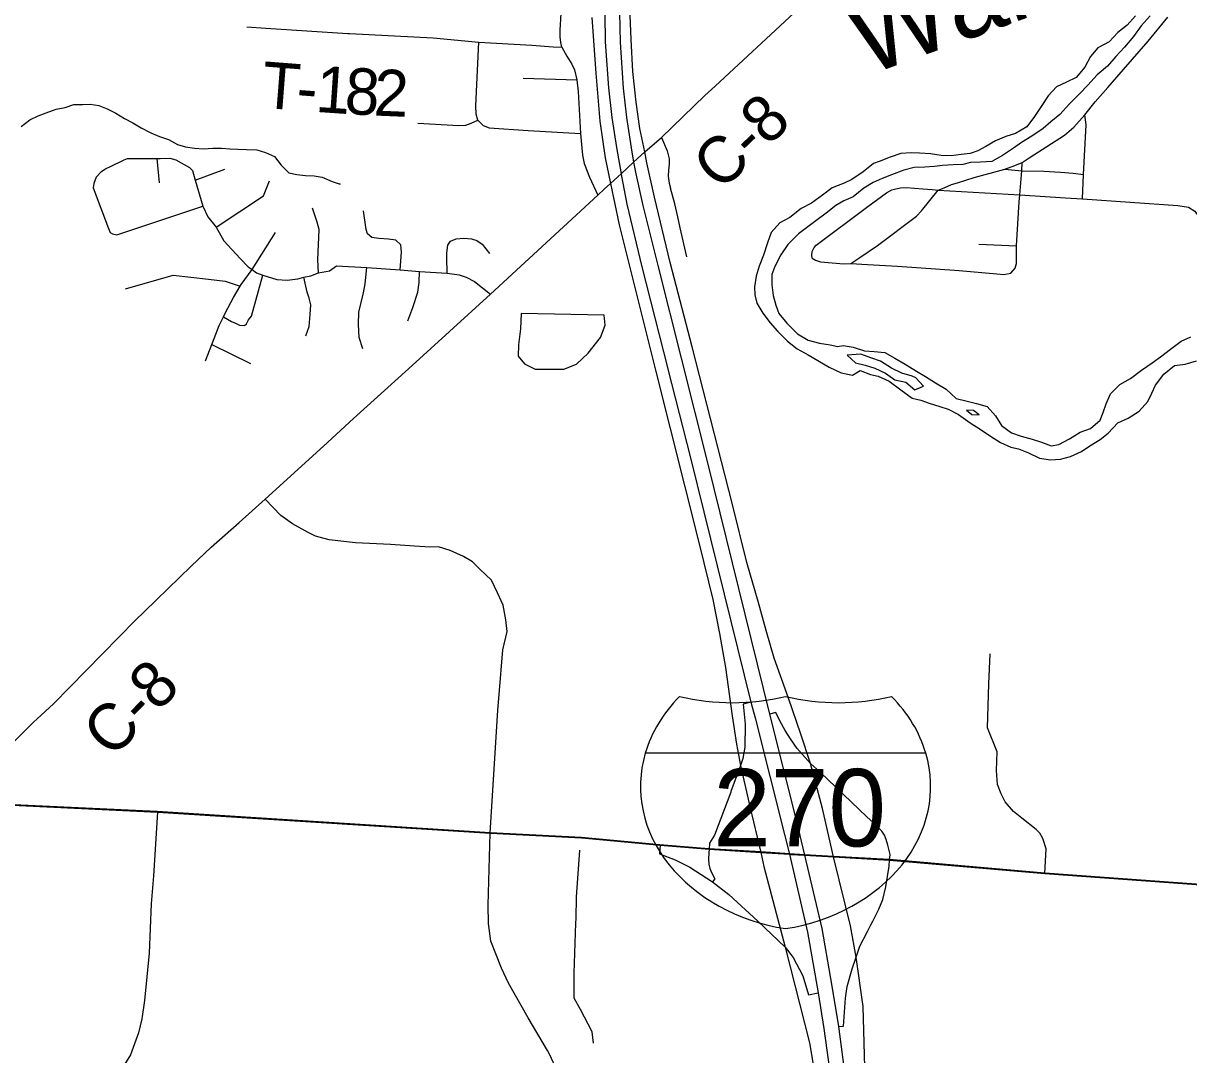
# Model space of a CAD drawing. Extents: x 0 to 34, y 0 to 22.
# Drawn here: x 5.335 to 6.761, y 16 to 17.262 of the extents above; entities that cross this region are included whole.
import ezdxf

# ---------------------------------------------------------------- set-up
doc = ezdxf.new("R2010")
doc.units = 0
for name, color, linetype in [('GM_X_City_Street', 7, 'Continuous'), ('GM_X_County_Road', 7, 'Continuous'), ('GM_X_County_Road_Text', 7, 'Continuous'), ('GM_X_Interchange_Ramps', 7, 'Continuous'), ('GM_X_Interstate_Location', 7, 'Continuous'), ('GM_X_Interstate_Route', 7, 'Continuous'), ('GM_X_Interstate_Shield', 7, 'Continuous'), ('GM_X_Major_River', 7, 'Continuous'), ('GM_X_Major_River_Text', 7, 'Continuous'), ('GM_X_Minor_Lake', 7, 'Continuous'), ('GM_X_Minor_River', 7, 'Continuous'), ('GM_X_Township_Road', 7, 'Continuous'), ('GM_X_Township_Road_Text', 7, 'Continuous')]:
    doc.layers.add(name, color=color, linetype=linetype)

msp = doc.modelspace()

# ---------------------------------------------------------------- linework, layer by layer
at = {"layer": 'GM_X_City_Street'}
for p, q in [((5.6084, 17.2578), (5.6319, 17.2559)), ((5.9467, 17.1948), (6.0123, 17.1929)), ((5.5015, 17.067), (5.4987, 17.0966)), ((5.5454, 17.07), (5.5815, 17.0837)), ((5.6149, 16.9609), (5.6436, 17.006)), ((6.5039, 16.9917), (6.5499, 16.9899)), ((5.5657, 16.869), (5.6129, 16.8458))]:
    msp.add_line(p, q, dxfattribs=at)
for points in [[(5.9939, 17.2327), (5.9927, 17.2383), (5.9918, 17.2453), (5.9918, 17.2535), (5.993, 17.2739)], [(6.2999, 16.9746), (6.2995, 16.9783), (6.3002, 16.983), (6.3026, 16.9877), (6.3051, 16.9905), (6.3682, 17.038), (6.3912, 17.0545), (6.3974, 17.0581), (6.4025, 17.0595), (6.408, 17.0608), (6.4149, 17.0612), (6.4354, 17.0594), (6.447, 17.0588), (6.4542, 17.0579), (6.4617, 17.0607), (6.4707, 17.0646), (6.4779, 17.0668), (6.4981, 17.0734), (6.5356, 17.0837), (6.5482, 17.0881), (6.5569, 17.0916), (6.5656, 17.0976), (6.6087, 17.1251), (6.6201, 17.1351), (6.6338, 17.1499), (6.6464, 17.1658), (6.6619, 17.1835), (6.7111, 17.2403), (6.7352, 17.2694)], [(5.8911, 17.1436), (5.8889, 17.1509), (5.8885, 17.1612), (5.8921, 17.2387)], [(5.8175, 17.14), (5.868, 17.1371), (5.8765, 17.1375), (5.883, 17.1399), (5.8911, 17.1436)], [(5.8911, 17.1436), (5.8976, 17.1369), (5.9051, 17.1339), (5.9526, 17.131), (6.0165, 17.1271)], [(6.6309, 17.0471), (6.632, 17.077), (6.6353, 17.1377), (6.6338, 17.1499)], [(5.4243, 17.0738), (5.4305, 17.0805), (5.4348, 17.0834), (5.4544, 17.0929), (5.4586, 17.0951), (5.4626, 17.0965), (5.4961, 17.0967), (5.4987, 17.0966), (5.5025, 17.0966), (5.5143, 17.0969), (5.5218, 17.0949), (5.5384, 17.0856), (5.5418, 17.0818), (5.5454, 17.07)], [(6.5356, 17.0837), (6.5567, 17.0815), (6.5833, 17.0809), (6.6039, 17.08), (6.6192, 17.0785), (6.632, 17.077)], [(6.543, 16.9562), (6.5486, 16.9623), (6.5499, 16.9682), (6.5499, 16.9899), (6.5532, 17.0435), (6.5541, 17.0522), (6.5567, 17.0815), (6.5569, 17.0916)], [(5.4243, 17.0738), (5.4212, 17.0659), (5.4204, 17.0606), (5.4392, 17.0111), (5.4414, 17.0061), (5.4441, 17.0046), (5.4494, 17.0034), (5.5547, 17.0381)], [(5.5454, 17.07), (5.5547, 17.0381), (5.5609, 17.0254), (5.5708, 17.0126), (5.5803, 16.996), (5.6002, 16.9742), (5.6103, 16.9642), (5.6149, 16.9609), (5.6204, 16.9569), (5.6279, 16.9538), (5.6453, 16.9487), (5.6578, 16.9478), (5.6707, 16.9496), (5.6781, 16.9513), (5.6867, 16.9532), (5.6962, 16.9567), (5.7094, 16.9591), (5.7182, 16.9652), (5.7551, 16.9631), (5.7962, 16.9605), (5.8198, 16.9582), (5.8534, 16.9565), (5.8682, 16.9543), (5.8766, 16.9514), (5.8868, 16.9463), (5.9065, 16.9306)], [(5.5708, 17.0126), (5.6289, 17.051), (5.6363, 17.0691)], [(6.1469, 16.9765), (6.1386, 17.0119), (6.1358, 17.0251), (6.132, 17.0412), (6.1267, 17.0604)], [(6.3473, 16.9683), (6.3583, 16.9755), (6.3798, 16.9902), (6.4278, 17.0261), (6.4339, 17.0326), (6.4542, 17.0579)], [(6.4542, 17.0579), (6.5541, 17.0522), (6.61, 17.0483), (6.6309, 17.0471), (6.7473, 17.0393), (6.7603, 17.0371), (6.7684, 17.0323), (6.7728, 17.0256), (6.7751, 17.0168), (6.7743, 17.0001), (6.7758, 16.9901), (6.778, 16.9853), (6.7861, 16.9783), (6.7969, 16.975), (6.8405, 16.9724), (6.8756, 16.9717), (6.9809, 16.9547)], [(5.6962, 16.9567), (5.6952, 16.9725), (5.6971, 17.0097), (5.6945, 17.0188), (5.689, 17.036)], [(5.7962, 16.9605), (5.7976, 16.982), (5.7967, 16.9911), (5.7908, 16.9965), (5.7817, 16.9981), (5.7698, 16.9986), (5.7612, 17), (5.7562, 17.0044), (5.7546, 17.0099), (5.7511, 17.0327)], [(5.8534, 16.9565), (5.853, 16.9754), (5.8532, 16.9813), (5.8543, 16.9904), (5.8578, 16.9954), (5.8644, 16.9982), (5.8739, 16.999), (5.8832, 16.9982), (5.8897, 16.9961), (5.8963, 16.9919), (5.9054, 16.9802)], [(6.2999, 16.9746), (6.304, 16.9722), (6.3103, 16.9702), (6.339, 16.9677), (6.3473, 16.9683), (6.3676, 16.967), (6.4043, 16.9649), (6.4799, 16.9596), (6.5258, 16.9557), (6.5345, 16.9549), (6.543, 16.9562)], [(5.4601, 16.9372), (5.5182, 16.9538), (5.5617, 16.9488), (5.5821, 16.9467), (5.6003, 16.9406)], [(5.558, 16.849), (5.5657, 16.869), (5.5666, 16.8713), (5.5747, 16.8925), (5.5798, 16.9029), (5.5821, 16.9076), (5.5921, 16.9265), (5.6003, 16.9406), (5.6014, 16.9423), (5.6149, 16.9609)], [(5.5798, 16.9029), (5.5899, 16.8973), (5.5956, 16.8949), (5.5997, 16.8926), (5.6058, 16.8922), (5.6081, 16.8944), (5.6104, 16.8993), (5.6142, 16.9038), (5.6279, 16.9538)], [(5.6806, 16.8797), (5.6849, 16.891), (5.6858, 16.9058), (5.6867, 16.9176), (5.6849, 16.9259), (5.6823, 16.9332), (5.6781, 16.9513)], [(5.7504, 16.8638), (5.7457, 16.8778), (5.745, 16.8937), (5.7453, 16.9086), (5.7511, 16.9322), (5.7534, 16.9432), (5.7551, 16.9631)], [(5.8055, 16.8981), (5.8116, 16.9142), (5.8175, 16.9329), (5.8191, 16.9451), (5.8198, 16.9582)], [(6.5847, 16.222), (6.5864, 16.2522), (6.5821, 16.2649), (6.5784, 16.2713), (6.574, 16.2759), (6.5566, 16.2897), (6.5462, 16.2977), (6.5362, 16.3097), (6.5312, 16.3195), (6.5268, 16.3308), (6.5255, 16.3479), (6.5262, 16.3707), (6.5145, 16.4004), (6.5162, 16.4539), (6.5179, 16.4906)], [(5.4991, 16.2971), (5.4941, 16.2193), (5.4913, 16.1851), (5.4888, 16.1248), (5.4834, 16.0669), (5.4802, 16.0443), (5.4758, 16.027), (5.4661, 16.0004), (5.4486, 15.9722), (5.4357, 15.9514), (5.4266, 15.9386), (5.4187, 15.9225), (5.4119, 15.9062), (5.4097, 15.8987), (5.4079, 15.8916), (5.4039, 15.8634), (5.4034, 15.8376), (5.403, 15.8068), (5.397, 15.7237), (5.3963, 15.6548), (5.395, 15.6065), (5.3941, 15.5706), (5.3958, 15.5456), (5.3958, 15.4747)], [(6.0325, 16.0147), (6.0311, 16.0282), (6.0168, 16.0557), (6.0088, 16.0696), (6.0091, 16.1003), (6.0111, 16.1613), (6.0113, 16.1672), (6.0117, 16.1932), (6.0158, 16.2504)]]:
    msp.add_lwpolyline(points, dxfattribs=at)
at = {"layer": 'GM_X_County_Road'}
msp.add_line((5.3406, 16.4002), (5.3476, 16.4072), dxfattribs=at)
for points in [[(6.1813, 17.1852), (6.3745, 17.3648), (6.5248, 17.5102), (6.5981, 17.5821), (6.6226, 17.6074), (6.632, 17.6186), (6.6405, 17.6299), (6.6463, 17.639), (6.6511, 17.6472), (6.6555, 17.6548), (6.6616, 17.6661), (6.6675, 17.6806), (6.6714, 17.6936), (6.6742, 17.7018), (6.6745, 17.7027)], [(6.0456, 17.059), (6.0535, 17.0662), (6.0664, 17.078), (6.0814, 17.092), (6.0952, 17.1048), (6.1156, 17.1224), (6.1688, 17.1735), (6.1813, 17.1852)], [(5.5487, 16.6058), (5.565, 16.621), (5.5989, 16.6512), (5.6311, 16.6797), (5.7021, 16.7449), (5.7389, 16.7787), (5.8062, 16.8393), (5.9065, 16.9306), (6.0378, 17.0517), (6.0456, 17.059)], [(5.9172, 16.4408), (5.9218, 16.4955), (5.9268, 16.5182), (5.9255, 16.5323), (5.922, 16.5502), (5.9152, 16.5655), (5.9077, 16.5809), (5.8941, 16.5937), (5.8845, 16.6033), (5.8736, 16.6097), (5.8572, 16.6173), (5.8429, 16.6218), (5.8322, 16.6212), (5.8137, 16.6226), (5.7841, 16.6245), (5.7415, 16.6266), (5.7092, 16.6301), (5.6926, 16.6348), (5.6834, 16.6391), (5.6643, 16.6498), (5.6502, 16.6598), (5.6311, 16.6797)], [(5.4834, 16.5425), (5.5405, 16.5981), (5.5487, 16.6058)], [(5.3476, 16.4072), (5.3518, 16.4114), (5.3721, 16.4296), (5.4718, 16.5313), (5.4834, 16.5425)], [(5.9063, 16.2713), (5.9156, 16.4219), (5.9172, 16.4408)], [(5.2617, 16.3084), (5.2893, 16.3473), (5.3052, 16.3647), (5.3204, 16.3801), (5.3399, 16.3995), (5.3406, 16.4002)], [(5.2615, 16.3089), (5.4989, 16.2977), (5.9061, 16.2718), (6.0177, 16.2662), (6.1138, 16.2573), (6.1738, 16.2523), (6.2371, 16.2484), (6.2723, 16.246), (6.2905, 16.245), (6.3259, 16.243), (6.3946, 16.239), (6.5845, 16.2226), (6.9775, 16.1941), (7.1913, 16.1774), (7.4185, 16.1629), (7.5307, 16.155), (7.5899, 16.1511), (7.7224, 16.142), (8.0841, 16.1202)], [(8.0841, 16.1202), (7.7224, 16.142), (7.5899, 16.1511), (7.5307, 16.155), (7.4185, 16.1629), (7.1913, 16.1774), (6.9775, 16.1941), (6.5845, 16.2226), (6.3946, 16.239), (6.3259, 16.243), (6.2905, 16.245), (6.2723, 16.246), (6.2371, 16.2484), (6.1738, 16.2523), (6.1138, 16.2573), (6.0177, 16.2662), (5.9061, 16.2718), (5.4989, 16.2977), (5.2615, 16.3089)], [(5.2617, 16.3084), (5.4991, 16.2971), (5.9063, 16.2713), (6.018, 16.2657), (6.0267, 16.2649)], [(5.9761, 16.0057), (5.9528, 16.0456), (5.9287, 16.0877), (5.9201, 16.1062), (5.907, 16.1391), (5.9043, 16.1607), (5.9037, 16.1834), (5.9063, 16.2713)], [(6.0267, 16.2649), (6.114, 16.2567), (6.174, 16.2518)], [(6.174, 16.2518), (6.2374, 16.2478), (6.2725, 16.2455), (6.2745, 16.2454)], [(6.2745, 16.2454), (6.2907, 16.2444), (6.3262, 16.2424), (6.3948, 16.2385)], [(6.3948, 16.2385), (6.5847, 16.222), (6.9777, 16.1936), (7.1915, 16.1769), (7.4187, 16.1623), (7.531, 16.1545), (7.5902, 16.1505), (7.7226, 16.1415), (8.0843, 16.1197), (8.277, 16.1089)], [(5.9763, 15.5648), (5.9785, 15.6152), (5.9878, 15.7911), (5.9894, 15.8846), (5.9918, 15.9482), (5.9908, 15.9667), (5.9879, 15.9813), (5.9793, 16.0003), (5.9761, 16.0057)]]:
    msp.add_lwpolyline(points, dxfattribs=at)
at = {"layer": 'GM_X_Interchange_Ramps'}
for points in [[(6.0306, 17.269), (6.0353, 17.201), (6.0402, 17.1424), (6.0469, 17.0976), (6.0535, 17.0662), (6.064, 17.0153), (6.1084, 16.8377), (6.1623, 16.6238), (6.1787, 16.5571), (6.1869, 16.5155), (6.1939, 16.4742), (6.2022, 16.415), (6.2074, 16.3803), (6.2123, 16.3543), (6.2237, 16.304), (6.2374, 16.2478), (6.2408, 16.2307), (6.2671, 16.1321), (6.2967, 16.015), (6.3167, 15.8958)], [(6.3648, 15.9703), (6.3623, 16.0595), (6.3537, 16.1197), (6.347, 16.1582), (6.3262, 16.2424), (6.3127, 16.3016), (6.2982, 16.3565), (6.2862, 16.3926), (6.2713, 16.4363), (6.2536, 16.4856), (6.2438, 16.5192), (6.2341, 16.5546), (6.2201, 16.6025), (6.2028, 16.6735), (6.1533, 16.8663), (6.1265, 16.9695), (6.1073, 17.0491), (6.0979, 17.0914), (6.0952, 17.1048), (6.0893, 17.1331), (6.0848, 17.1655), (6.0808, 17.2031), (6.0788, 17.2421), (6.0774, 17.2718)], [(6.2252, 16.4318), (6.2155, 16.429), (6.2182, 16.4045), (6.2177, 16.3764), (6.2154, 16.3628), (6.2123, 16.3543), (6.2007, 16.3225)], [(6.3948, 16.2385), (6.3956, 16.2454), (6.3926, 16.2569), (6.3906, 16.2637), (6.3885, 16.269), (6.3852, 16.2738), (6.3796, 16.2798), (6.367, 16.2913), (6.3099, 16.3459), (6.2982, 16.3565), (6.2817, 16.3751), (6.2736, 16.3866), (6.267, 16.3971), (6.2606, 16.4087), (6.2558, 16.419), (6.2478, 16.4169)], [(6.2007, 16.3225), (6.2004, 16.3215), (6.1806, 16.269), (6.1745, 16.259), (6.174, 16.2518)], [(6.114, 16.2567), (6.1133, 16.2459), (6.1324, 16.2389), (6.1504, 16.2298), (6.178, 16.2117)], [(6.174, 16.2518), (6.1737, 16.2474), (6.1731, 16.2395), (6.1735, 16.2334), (6.1748, 16.2283), (6.1775, 16.2226), (6.1811, 16.2156), (6.178, 16.2117)], [(6.3717, 16.1591), (6.3743, 16.1639), (6.3818, 16.1785), (6.3865, 16.1902), (6.3902, 16.2057), (6.3941, 16.2309), (6.3948, 16.2385)], [(6.178, 16.2117), (6.1983, 16.1962), (6.2334, 16.1637), (6.2671, 16.1321), (6.2768, 16.1194), (6.2885, 16.0969), (6.2956, 16.0735), (6.3073, 16.076)], [(6.3321, 16.0348), (6.3382, 16.0355), (6.3408, 16.0696), (6.343, 16.0838), (6.3488, 16.1055), (6.3537, 16.1197), (6.3583, 16.133), (6.3677, 16.1513), (6.3717, 16.1591)]]:
    msp.add_lwpolyline(points, dxfattribs=at)
at = {"layer": 'GM_X_Interstate_Route'}
for points in [[(6.0806, 17.8866), (6.0801, 17.8781), (6.0749, 17.7945), (6.0705, 17.7209), (6.0641, 17.6239), (6.0455, 17.3114), (6.0469, 17.2452)], [(6.0635, 17.3111), (6.065, 17.2389), (6.069, 17.1828), (6.0729, 17.1466), (6.0786, 17.1097), (6.0814, 17.092), (6.0844, 17.0777), (6.0931, 17.0391), (6.1115, 16.9641), (6.14, 16.8524), (6.172, 16.7243), (6.2478, 16.4169), (6.2811, 16.2857), (6.2907, 16.2444), (6.3118, 16.1548), (6.3243, 16.0844), (6.3321, 16.0348), (6.3409, 15.9698), (6.3497, 15.8891), (6.3545, 15.8244), (6.3582, 15.7404), (6.3582, 15.7334)], [(6.0469, 17.2452), (6.047, 17.2392), (6.051, 17.1831), (6.0549, 17.1469), (6.0606, 17.11), (6.0664, 17.078), (6.0669, 17.075)], [(6.0669, 17.075), (6.0733, 17.0409), (6.0918, 16.9642), (6.1183, 16.8602), (6.1281, 16.8215)], [(6.1281, 16.8215), (6.1512, 16.7304), (6.2252, 16.4318)], [(6.2252, 16.4318), (6.2302, 16.4124), (6.2663, 16.2697)], [(6.2663, 16.2697), (6.2725, 16.2455), (6.2942, 16.1503), (6.3073, 16.076), (6.3144, 16.0325), (6.3232, 15.9676), (6.3319, 15.8868), (6.335, 15.8335), (6.3387, 15.7419), (6.3382, 15.6997)]]:
    msp.add_lwpolyline(points, dxfattribs=at)
at = {"layer": 'GM_X_Interstate_Shield'}
msp.add_line((6.4392, 16.3691), (6.0958, 16.3691), dxfattribs=at)
msp.add_line((6.4392, 16.3691), (6.0958, 16.3691), dxfattribs=at)
for centre, start_param, end_param in [((6.3119, 16.3285), 2.47259, 2.911027), ((6.2027, 16.6085), 4.415841, 5.008937), ((6.3324, 16.6085), 4.415841, 5.008937), ((6.2231, 16.3285), 0.230566, 0.669003), ((6.3119, 16.3285), 2.911027, 4.511031), ((6.2231, 16.3285), 4.913747, 6.513751)]:
    msp.add_ellipse(centre, major_axis=(0.2219, 0), ratio=0.8, start_param=start_param, end_param=end_param, dxfattribs=at)
at = {"layer": 'GM_X_Major_River'}
for points in [[(6.7134, 17.2711), (6.7024, 17.259), (6.6932, 17.2458), (6.6821, 17.2329), (6.6715, 17.2212), (6.6612, 17.2095), (6.6486, 17.1989), (6.6375, 17.1864), (6.6269, 17.1751), (6.6147, 17.1633), (6.6032, 17.1505), (6.5922, 17.1414), (6.5827, 17.1331), (6.5689, 17.1241), (6.556, 17.1161), (6.5465, 17.1094), (6.5328, 17.1003), (6.5199, 17.0931), (6.5058, 17.0921), (6.4937, 17.0917), (6.4842, 17.0891), (6.4724, 17.0888), (6.4595, 17.0881), (6.4497, 17.0866), (6.4379, 17.0859), (6.425, 17.0856), (6.4121, 17.0822), (6.3973, 17.0766), (6.3859, 17.0721), (6.3745, 17.0672), (6.3634, 17.0601), (6.3501, 17.0499), (6.3387, 17.045), (6.3292, 17.039), (6.317, 17.0299), (6.3044, 17.0205), (6.2949, 17.0129), (6.2835, 17.0046), (6.2705, 16.9914), (6.2617, 16.9789), (6.2545, 16.9645), (6.2506, 16.9546), (6.2506, 16.9421), (6.2524, 16.9292), (6.2557, 16.917), (6.2591, 16.9071), (6.2689, 16.8953), (6.2821, 16.8823), (6.295, 16.8743), (6.309, 16.8708), (6.3219, 16.8685), (6.3313, 16.8665)], [(6.6956, 17.2712), (6.6853, 17.2598), (6.6739, 17.2508), (6.6632, 17.2394), (6.6495, 17.2319), (6.6404, 17.2213), (6.6335, 17.2084), (6.6232, 17.1956), (6.6114, 17.1899), (6.5988, 17.1843), (6.5889, 17.1733), (6.5809, 17.1616), (6.5721, 17.148), (6.5626, 17.1355), (6.5489, 17.1272), (6.5371, 17.1234), (6.5245, 17.1182), (6.5124, 17.1114), (6.5029, 17.1058), (6.4934, 17.1028), (6.4824, 17.1013), (6.4702, 17.0998), (6.4577, 17.1003), (6.4448, 17.1022), (6.4315, 17.103), (6.4213, 17.1035), (6.4084, 17.1028), (6.3955, 17.0983), (6.3822, 17.093)], [(6.3822, 17.093), (6.375, 17.0904), (6.3624, 17.0802), (6.3487, 17.0708), (6.3392, 17.0663), (6.3244, 17.0606), (6.3126, 17.0516), (6.2992, 17.0421), (6.2867, 17.0354), (6.2726, 17.0244), (6.2604, 17.018), (6.2501, 17.0059), (6.2455, 16.9934), (6.2405, 16.9782), (6.2351, 16.965), (6.2316, 16.9525), (6.2297, 16.9395), (6.23, 16.9297), (6.2322, 16.9198), (6.2398, 16.9076), (6.2488, 16.8954), (6.2575, 16.8855), (6.2699, 16.8733), (6.2816, 16.8637), (6.2953, 16.8565), (6.321, 16.8412), (6.3354, 16.8343), (6.3494, 16.8315), (6.3589, 16.8372), (6.3714, 16.8322), (6.3809, 16.8302), (6.3941, 16.8241), (6.4085, 16.8138), (6.4224, 16.8035), (6.433, 16.8008), (6.4433, 16.7973), (6.4561, 16.7934), (6.4664, 16.79), (6.4789, 16.7835), (6.4932, 16.7731), (6.5057, 16.7655), (6.5182, 16.7571), (6.5303, 16.7494), (6.5431, 16.7437), (6.5526, 16.7414), (6.5647, 16.7364), (6.5783, 16.7302), (6.5916, 16.7279), (6.6038, 16.729), (6.6159, 16.7319), (6.6296, 16.7383), (6.6399, 16.7451), (6.6524, 16.753), (6.6623, 16.7606), (6.6738, 16.7734), (6.6867, 16.7791), (6.7, 16.7874), (6.7107, 16.7995), (6.7157, 16.8097), (6.7199, 16.8192), (6.7302, 16.8328), (6.7432, 16.8434), (6.7564, 16.8452), (6.7701, 16.8493)], [(6.3313, 16.8665), (6.3378, 16.868), (6.3503, 16.8657), (6.3639, 16.8615), (6.3761, 16.8606), (6.389, 16.8591), (6.4011, 16.8522), (6.4139, 16.8449), (6.4275, 16.8365), (6.4389, 16.83), (6.451, 16.8223), (6.4638, 16.8143), (6.4763, 16.8032), (6.488, 16.8001), (6.5013, 16.797), (6.5142, 16.7932), (6.5244, 16.7817), (6.5315, 16.7699), (6.544, 16.7611), (6.5557, 16.7569), (6.569, 16.7534), (6.5807, 16.7496), (6.5925, 16.745), (6.6019, 16.7468), (6.6149, 16.7536), (6.6278, 16.7619), (6.6404, 16.7664), (6.6525, 16.7766), (6.656, 16.7861), (6.6598, 16.7967), (6.6652, 16.8088), (6.6763, 16.8201), (6.6896, 16.8273), (6.7029, 16.8375), (6.7159, 16.8465), (6.7261, 16.8541), (6.7383, 16.8635), (6.7513, 16.8733), (6.7634, 16.8786)], [(6.4267, 16.8285), (6.4222, 16.8304), (6.4097, 16.8339), (6.3972, 16.84), (6.3836, 16.8485), (6.3719, 16.8527), (6.3597, 16.8573), (6.3427, 16.8559)], [(6.3427, 16.8559), (6.3532, 16.8467), (6.365, 16.844), (6.3767, 16.8401), (6.3896, 16.834), (6.4013, 16.826), (6.4146, 16.8229), (6.4255, 16.8137), (6.4362, 16.8182), (6.4267, 16.8285)], [(6.4887, 16.7887), (6.4955, 16.7834), (6.5043, 16.783)], [(6.5043, 16.783), (6.4975, 16.7883), (6.4887, 16.7887)]]:
    msp.add_lwpolyline(points, dxfattribs=at)
at = {"layer": 'GM_X_Minor_Lake'}
for points in [[(5.9442, 16.9068), (5.9433, 16.8882), (5.9408, 16.8685), (5.9403, 16.8549), (5.9481, 16.8453), (5.9614, 16.8391), (5.9781, 16.8389), (5.9963, 16.8391), (6.0119, 16.845), (6.0261, 16.8586), (6.0411, 16.8778), (6.0469, 16.8929), (6.0455, 16.9051)], [(6.0455, 16.9051), (5.9442, 16.9068)]]:
    msp.add_lwpolyline(points, dxfattribs=at)
at = {"layer": 'GM_X_Minor_River'}
msp.add_lwpolyline([(5.3324, 17.1357), (5.3431, 17.1439), (5.3534, 17.1488), (5.3629, 17.1525), (5.3751, 17.1569), (5.3861, 17.1591), (5.3967, 17.1628), (5.4074, 17.1627), (5.4168, 17.163), (5.4274, 17.1614), (5.4376, 17.1575), (5.4482, 17.1521), (5.4587, 17.1455), (5.4689, 17.1401), (5.4791, 17.1339), (5.4912, 17.1281), (5.5017, 17.1235), (5.5127, 17.1199), (5.5236, 17.1138), (5.5335, 17.111), (5.5444, 17.1094), (5.5554, 17.1085), (5.5668, 17.1092), (5.5774, 17.1091), (5.5876, 17.1086), (5.5975, 17.1081), (5.6081, 17.1077), (5.6206, 17.1072), (5.6312, 17.104), (5.6425, 17.099), (5.6504, 17.0886), (5.6598, 17.0791), (5.6696, 17.0771), (5.6802, 17.0758), (5.6908, 17.0753), (5.7006, 17.0737), (5.7127, 17.0683), (5.7225, 17.0652), (5.7218, 17.0656)], dxfattribs=at)
at = {"layer": 'GM_X_Township_Road'}
msp.add_line((5.6319, 17.2559), (5.732, 17.2496), dxfattribs=at)
for points in [[(5.732, 17.2496), (5.734, 17.2495), (5.8366, 17.2442), (5.8921, 17.2387), (5.9572, 17.2351), (5.9831, 17.233), (5.9939, 17.2327), (5.9999, 17.2217), (6.0062, 17.212), (6.0092, 17.2051), (6.0123, 17.1929), (6.0136, 17.1784), (6.0165, 17.1271), (6.0181, 17.1092), (6.019, 17.1005), (6.0211, 17.0903), (6.0275, 17.0738), (6.0378, 17.0517)], [(6.1156, 17.1224), (6.1227, 17.1058), (6.1253, 17.0962), (6.125, 17.0895), (6.1245, 17.0823), (6.1241, 17.0749), (6.1253, 17.0664), (6.1267, 17.0604)]]:
    msp.add_lwpolyline(points, dxfattribs=at)

# ---------------------------------------------------------------- texts
at = {"layer": 'GM_X_County_Road_Text'}
for rotation, p in [(43.7295, (6.1882, 17.0552)), (45.6495, (5.4436, 16.3614))]:
    msp.add_text('C-8', height=0.05682, rotation=rotation, dxfattribs=at).set_placement(p)
at = {"layer": 'GM_X_Interstate_Location'}
for s in ['.', '-', ',']:
    msp.add_text(s, height=0.000189, dxfattribs=at).set_placement((6.2675, 16.3024))
msp.add_text('270', height=0.000189, rotation=0, dxfattribs=at).set_placement((6.2096, 16.2632))
at = {"layer": 'GM_X_Interstate_Shield'}
msp.add_text('270', height=0.0947, dxfattribs=at).set_placement((6.1791, 16.2552))
at = {"layer": 'GM_X_Major_River_Text'}
msp.add_text('Walnut', height=0.0947, rotation=20.0045, dxfattribs=at).set_placement((6.3658, 17.1969))
at = {"layer": 'GM_X_Township_Road_Text'}
for s, rotation, p in [('T', 355.5471, (5.6253, 17.1588)), ('1', 356.088, (5.6915, 17.1537)), ('8', 356.7534, (5.7272, 17.1513)), ('2', 357.6145, (5.763, 17.1492)), ('-', 355.6867, (5.6678, 17.1555))]:
    msp.add_text(s, height=0.0568, rotation=rotation, dxfattribs=at).set_placement(p)

doc.saveas('drawing.dxf')
